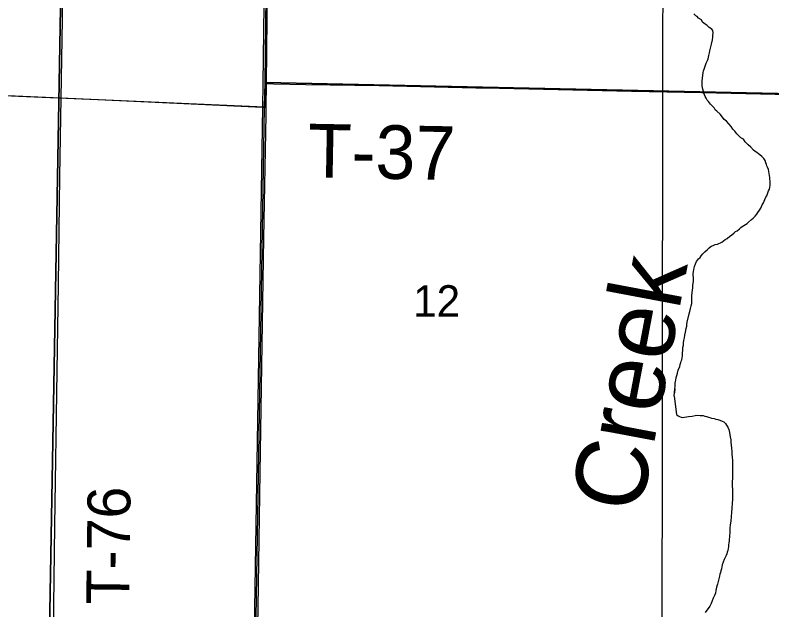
# Model space of a CAD drawing. Extents: x 0 to 68, y 0 to 52.9.
# Drawn here: x 42.738 to 43.796, y 33.293 to 34.125 of the extents above; entities that cross this region are included whole.
import ezdxf

# ---------------------------------------------------------------- set-up
doc = ezdxf.new("R2010")
doc.units = 0
for name, color, linetype in [('Default', 7, 'Continuous'), ('GM_X_County_Road', 7, 'Continuous'), ('GM_X_Minor_River', 7, 'Continuous'), ('GM_X_Minor_River_Text', 7, 'Continuous'), ('GM_X_Township', 7, 'Continuous'), ('GM_X_Township_Road', 7, 'Continuous'), ('GM_X_Township_Road_Text', 7, 'Continuous')]:
    doc.layers.add(name, color=color, linetype=linetype)

msp = doc.modelspace()

# ---------------------------------------------------------------- linework, layer by layer
at = {"layer": 'Default'}
for points in [[(43.6416, 32.7683), (43.6433, 34.0176), (43.6445, 34.6783), (43.656, 35.3485), (43.6679, 36.0083), (43.677, 36.4459), (43.686, 36.8454), (43.6904, 37.0468), (43.6959, 37.2899), (43.6976, 37.3155), (43.7023, 37.357), (43.7061, 37.3835), (43.7187, 37.4504), (43.791, 37.8727), (43.7942, 37.8955), (43.7959, 37.9156), (43.7976, 37.9355), (43.7985, 37.9597), (43.7994, 37.991), (43.8015, 38.1232), (43.8073, 38.5411), (43.8097, 38.7192)], [(42.2581, 34.3055), (42.8041, 34.2941), (42.7855, 33.2374), (42.2581, 33.2485)], [(43.0687, 32.7683), (43.0718, 32.9599), (43.0739, 33.0953), (43.0773, 33.2962), (43.0801, 33.4849), (43.0852, 33.813), (43.0885, 33.9853), (43.0886, 33.9958), (43.089, 34.0291), (43.0906, 34.1657)], [(43.0661, 32.7683), (43.0864, 33.9961), (43.0873, 34.0306), (44.3032, 34.0046), (44.2875, 32.7683)]]:
    msp.add_lwpolyline(points, dxfattribs=at)
for points in [[(41.7644, 35.3862), (43.1022, 35.3161), (43.0873, 34.0306), (43.0864, 33.9961), (41.7454, 34.0552)], [(43.1026, 35.3466), (43.6933, 35.3509), (44.3202, 35.3382), (44.3032, 34.0046), (43.0873, 34.0306), (43.1022, 35.3161)], [(42.8041, 34.2941), (43.8657, 34.2406), (43.8561, 33.2057), (43.8558, 33.1813), (42.7855, 33.2374)]]:
    msp.add_lwpolyline(points, close=True, dxfattribs=at)
at = {"layer": 'GM_X_County_Road'}
msp.add_lwpolyline([(42.4219, 34.0261), (42.4392, 34.0251), (42.4761, 34.0239), (42.6647, 34.0152), (42.7425, 34.0115), (42.8532, 34.0068), (43.0335, 33.9984), (43.0837, 33.9961), (43.0886, 33.9958)], dxfattribs=at)
at = {"layer": 'GM_X_Minor_River'}
for points in [[(43.791, 33.879), (43.7922, 33.8814), (43.7926, 33.8838), (43.7935, 33.8874), (43.7935, 33.8906), (43.7931, 33.893), (43.7927, 33.895), (43.7928, 33.8979), (43.7924, 33.9007), (43.7916, 33.9059), (43.7909, 33.9091), (43.7897, 33.912), (43.7885, 33.914), (43.7881, 33.916), (43.7873, 33.918), (43.7862, 33.9216), (43.7842, 33.9245), (43.7818, 33.9273), (43.779, 33.9294), (43.777, 33.931), (43.7746, 33.9326), (43.7722, 33.9342), (43.7698, 33.9359), (43.7662, 33.9403), (43.7627, 33.9436), (43.7603, 33.9456), (43.7583, 33.9477), (43.7559, 33.9513), (43.7523, 33.9533), (43.7495, 33.9562), (43.7467, 33.959), (43.7439, 33.9623), (43.7412, 33.9655), (43.7388, 33.9692), (43.7356, 33.9728), (43.7324, 33.9765), (43.7292, 33.9789), (43.7265, 33.9821), (43.7233, 33.9862), (43.7189, 33.9903), (43.7165, 33.9923), (43.7149, 33.9951), (43.7121, 33.998), (43.7098, 34.0004), (43.707, 34.004), (43.7054, 34.0061), (43.7038, 34.0085), (43.7022, 34.0109), (43.7014, 34.0133), (43.7007, 34.0158), (43.6999, 34.0182), (43.6991, 34.0214), (43.6987, 34.0234), (43.6983, 34.0258), (43.6984, 34.0286), (43.6984, 34.0323), (43.6993, 34.0411), (43.6997, 34.0443), (43.7002, 34.0471), (43.701, 34.0495), (43.7018, 34.0523), (43.7031, 34.0551), (43.7039, 34.0579), (43.7055, 34.0615), (43.7068, 34.0639), (43.7072, 34.0659), (43.7076, 34.0683), (43.708, 34.0703), (43.7084, 34.0723), (43.7089, 34.0748), (43.7097, 34.0788), (43.7106, 34.0824), (43.7114, 34.0844), (43.7126, 34.0904), (43.7131, 34.094), (43.7131, 34.096), (43.7135, 34.1), (43.7132, 34.1032), (43.7116, 34.1053), (43.708, 34.1077), (43.7052, 34.1102), (43.7024, 34.1122), (43.6988, 34.115), (43.6972, 34.1183), (43.6932, 34.1207), (43.6913, 34.1228), (43.6893, 34.124), (43.6865, 34.1268)], [(43.6591, 33.5918), (43.66, 33.6019), (43.6596, 33.5962), (43.66, 33.6019), (43.6605, 33.6059), (43.6605, 33.6079), (43.6605, 33.6099), (43.6609, 33.6123), (43.6613, 33.6143), (43.6618, 33.6179), (43.6626, 33.6207), (43.6635, 33.6239), (43.6647, 33.6283), (43.6668, 33.6331), (43.6676, 33.6359), (43.6684, 33.6387), (43.6688, 33.6407), (43.6697, 33.6427), (43.6701, 33.6456), (43.6705, 33.648), (43.6705, 33.65), (43.6706, 33.6524), (43.671, 33.6556), (43.6714, 33.66), (43.6719, 33.6632), (43.6723, 33.6664), (43.6727, 33.6696), (43.6736, 33.6732), (43.674, 33.6773), (43.6749, 33.6813), (43.6757, 33.6865), (43.6766, 33.6897), (43.677, 33.6921), (43.6774, 33.6953), (43.6799, 33.7069), (43.6808, 33.7101), (43.682, 33.7142), (43.6829, 33.7182), (43.6837, 33.7214), (43.6837, 33.7234), (43.6837, 33.7254), (43.6838, 33.7286), (43.6838, 33.7318), (43.6843, 33.737), (43.6847, 33.7402), (43.6851, 33.7431), (43.6851, 33.7451), (43.6852, 33.7471), (43.6856, 33.7495), (43.686, 33.7527), (43.686, 33.7551), (43.6861, 33.7579), (43.6857, 33.7611), (43.6857, 33.7631), (43.6862, 33.7664), (43.6866, 33.7684), (43.687, 33.7712), (43.6874, 33.7732), (43.6891, 33.7768), (43.6903, 33.78), (43.6915, 33.782), (43.6932, 33.784), (43.6952, 33.7859), (43.6968, 33.7883), (43.6993, 33.7907), (43.7021, 33.7939), (43.7057, 33.7971), (43.7078, 33.7995), (43.711, 33.8015), (43.7138, 33.8026), (43.7163, 33.8038), (43.7195, 33.8046), (43.7255, 33.8073), (43.7304, 33.8109), (43.7332, 33.8125), (43.7369, 33.8157), (43.7393, 33.8172), (43.743, 33.8204), (43.745, 33.822), (43.747, 33.8232), (43.7502, 33.826), (43.7523, 33.8276), (43.7543, 33.8291), (43.7587, 33.8319), (43.7612, 33.8335), (43.7632, 33.8351), (43.7673, 33.8391), (43.7693, 33.8406), (43.7725, 33.8438), (43.7746, 33.8462), (43.7762, 33.8486), (43.7782, 33.8522), (43.7803, 33.855), (43.7819, 33.8594), (43.784, 33.8622), (43.7848, 33.8646), (43.786, 33.867), (43.7873, 33.8702), (43.7885, 33.8722), (43.7897, 33.875), (43.791, 33.879)], [(43.6591, 33.5918), (43.6625, 33.5661), (43.6645, 33.5644), (43.6665, 33.5632), (43.6689, 33.5624), (43.6709, 33.562), (43.6733, 33.5623), (43.6761, 33.5627), (43.6793, 33.5631), (43.6842, 33.5638), (43.6882, 33.5646), (43.6918, 33.565), (43.6954, 33.5649), (43.6978, 33.5649), (43.6998, 33.5645), (43.7019, 33.564), (43.7043, 33.5632), (43.7071, 33.5624), (43.7091, 33.562), (43.7111, 33.5611), (43.7151, 33.5603), (43.7175, 33.5595), (43.7199, 33.559), (43.7231, 33.5582), (43.7263, 33.557), (43.7287, 33.5557), (43.7307, 33.5537), (43.7323, 33.5513), (43.7339, 33.5484), (43.7354, 33.5452), (43.7366, 33.5408), (43.7373, 33.5347), (43.7381, 33.5307), (43.7385, 33.5271), (43.7388, 33.5235), (43.7392, 33.5186), (43.7396, 33.5146), (43.7399, 33.5106), (43.7403, 33.5062), (43.7406, 33.5018), (43.7406, 33.4961), (43.7404, 33.4825), (43.7404, 33.4772), (43.7403, 33.472), (43.7403, 33.4668), (43.7406, 33.4608), (43.7406, 33.4543), (43.7405, 33.4475), (43.74, 33.4415), (43.7396, 33.4351), (43.7391, 33.429), (43.7387, 33.4234), (43.7382, 33.417), (43.7373, 33.4118), (43.7369, 33.4069), (43.7369, 33.4033), (43.7368, 33.4001), (43.7364, 33.3973), (43.7364, 33.3945), (43.7359, 33.3917), (43.7359, 33.3893), (43.7355, 33.3861), (43.7351, 33.3841), (43.735, 33.3812), (43.7346, 33.3788), (43.7342, 33.376), (43.7333, 33.3736), (43.7325, 33.3712), (43.7317, 33.3688), (43.7305, 33.366), (43.7292, 33.3632), (43.7276, 33.3596), (43.7263, 33.356), (43.7255, 33.3532), (43.7251, 33.35), (43.7242, 33.3476), (43.7238, 33.3452), (43.723, 33.3428), (43.7226, 33.34), (43.7217, 33.3364), (43.7205, 33.3324), (43.7196, 33.3288), (43.7184, 33.3244), (43.7175, 33.3199), (43.7167, 33.3163), (43.7155, 33.3131), (43.7138, 33.3091), (43.7122, 33.3055), (43.7109, 33.3015), (43.7089, 33.2979), (43.7024, 33.2892)]]:
    msp.add_lwpolyline(points, dxfattribs=at)
at = {"layer": 'GM_X_Township'}
msp.add_lwpolyline([(43.0644, 32.7683), (43.0839, 33.9959), (43.0844, 34.0287), (43.0925, 34.6527), (43.0929, 34.6864), (43.1046, 35.3142), (43.1053, 35.3456), (43.1113, 36.0138), (43.1191, 36.6427), (43.1235, 37.0176), (43.1252, 37.2584), (43.1291, 37.4252), (43.1246, 37.4931), (43.125, 37.5147), (43.132, 37.8314), (43.1321, 37.8584), (43.1323, 37.9511), (43.3145, 37.9477), (43.3203, 37.9479), (44.1214, 37.9431), (44.7776, 37.9316), (45.7636, 37.9078)], dxfattribs=at)
at = {"layer": 'GM_X_Township_Road'}
for points in [[(42.7913, 33.235), (42.7914, 33.2429), (42.7918, 33.2987), (42.7934, 33.4102), (42.7967, 33.6267), (42.7984, 33.7481), (42.8, 33.899), (42.8038, 34.1187), (42.8053, 34.2565), (42.806, 34.2933)], [(43.089, 34.0291), (43.0989, 34.0289), (43.144, 34.0278), (43.2466, 34.0264), (43.3819, 34.0232), (43.4147, 34.0226), (43.4967, 34.0206), (43.5992, 34.0185), (43.6976, 34.0166), (43.8001, 34.0144), (43.8822, 34.0135), (43.9478, 34.0122), (44.0052, 34.0113), (44.1282, 34.0089), (44.2431, 34.0069), (44.3743, 34.0041), (44.4317, 34.0025), (44.526, 34.0009), (44.6573, 33.9979), (44.7475, 33.9963), (44.8459, 33.994), (44.8991, 33.9924), (44.9746, 33.9909)]]:
    msp.add_lwpolyline(points, dxfattribs=at)

# ---------------------------------------------------------------- texts
at = {"layer": 'Default'}
msp.add_text('12', height=0.0442, rotation=0, dxfattribs=at).set_placement((43.2941, 33.7028))
at = {"layer": 'GM_X_Minor_River_Text'}
msp.add_text('Creek', height=0.10004, rotation=79.3151, dxfattribs=at).set_placement((43.6121, 33.4255))
at = {"layer": 'GM_X_Township_Road_Text'}
for s, height, rotation, p in [('T-37', 0.075, 358.9397, (43.1463, 33.898)), ('T-76', 0.06, 89.2917, (42.8971, 33.2999))]:
    msp.add_text(s, height=height, rotation=rotation, dxfattribs=at).set_placement(p)

doc.saveas('drawing.dxf')
